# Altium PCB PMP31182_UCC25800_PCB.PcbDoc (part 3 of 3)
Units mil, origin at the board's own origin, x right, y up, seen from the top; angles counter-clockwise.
Board outline 4922 x 2266 mil, 4 copper layers (Top Layer, Signal Layer 1, Signal Layer 2, Bottom Layer), stack 77.9 mil thick; 172 components, 94 nets, 533 pads, 516 vias.
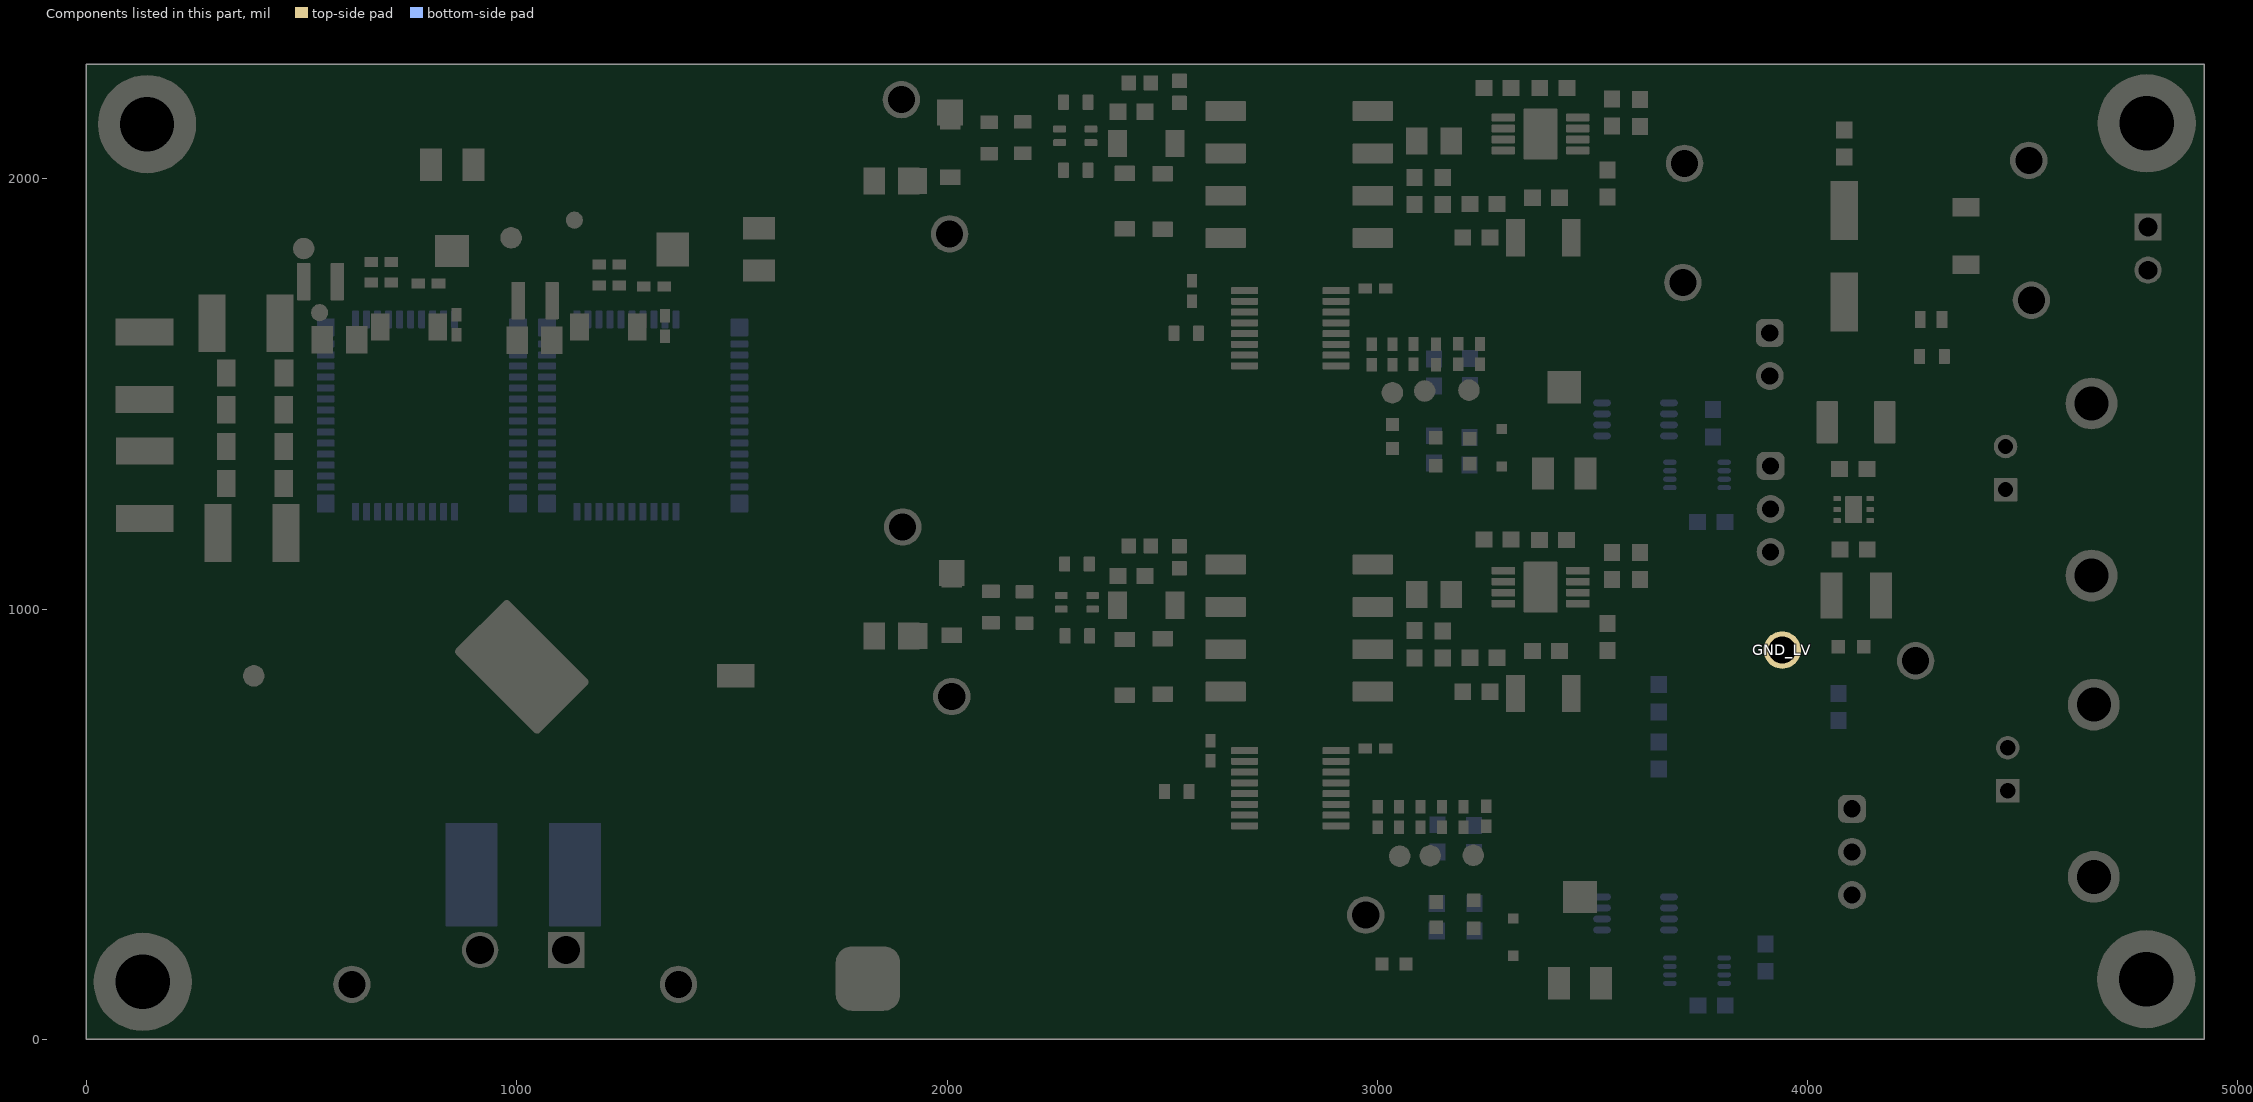
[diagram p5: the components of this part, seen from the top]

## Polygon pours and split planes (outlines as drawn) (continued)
NetT2_1 on Signal Layer 2 "NETT2_1_L03_P146" (solid, pour order 146): 3255,2078 3260,2083 3260,2107 3171.93,2195.07 3050.07,2195.07 3044,2187 3044,2138 3051,2131 3169,2131 3222,2078
HVBUS on Signal Layer 2 "HVBUS_L03_P054" (solid, remove dead copper, pour order 54): 376,22 317.88,64 317.88,192.12 79.88,430.12 79.88,1709.88 95,1725 342,1725 476,1591 476,1530 1406.59,1530 1491.2,1635.68 1531.32,1635.68 1538.88,1628.12 1538.88,1226.88 1525,1213 935,1213 758.88,1036.88 758.88,470.68 763.88,470.68 814.88,419.68 953.88,419.68 953.88,417.99 977.88,393.99 977.88,60 928,22
SW on Signal Layer 2 "SW_L03_P002" (solid, remove dead copper, pour order 2): 2691,653 2713,631 2713,484 2700,471 2475.05,471 1607,1289.18 1607,1637.45 1530.46,1714 1474,1714 1354,1594 984,1594 973,1605 973,1865 1022,1914 1530,1914 1960,1484 2586.56,857.45 2586.56,757.44
GND_LV on Signal Layer 2 "Signal Layer 1-GND_LV" (solid, pour order 158): 4759,1574 4859,1474 4859,415 4466,22 3172,22 3110,84 3110,269 3005,374 3005,441 2900,441 2898,439 2898,490 2996.53,490 3008,501.47 3008,1242 2937,1242 2936,1241 2934,1243 2934,1310 2987,1310 3008,1331 3008,1493 2977,1524 2977,1729 3078,1830 3078,2226.13 3091,2238 3583,2238 3841,2238 3864,2215 3864,1604.86 3895.74,1574
GND_HV on Signal Layer 2 "GND_HV_L03_P096" (solid, remove dead copper, pour order 96): 484,1655.47 484,2146 575,2237 2065,2237 2187,2237 2679,1745 2679,1579.01 2643.99,1544 2037,1544 1627,1954 957,1954 920,1917 920,1620 894,1594 545.48,1594
5V on Signal Layer 2 "5V_L03_P136" (solid, pour order 136): 4375.35,797.4 4114.35,797.4 4114.35,944.4 4118.35,948.4 4118.35,1110.4 4118.35,1156.4 4148.35,1186.4 4171.35,1186.4 4171.35,1223.4 4147.69,1247.06 4147.69,1251.4 4137.35,1251.4 4135.35,1253.4 4135.35,1263.4 4153.35,1263.4 4375.35,1263.4
GND_LV on Signal Layer 1 "Signal Layer 1-GND_LV" (solid, pour order 134): 4770,1575 4859,1486 4859,416 4466,23 3172,23 3110,85 3110,270 3005,375 3005,442 2900,442 2898,440 2898,491 2996.53,491 3008,502.47 3008,1243 2937,1243 2936,1242 2934,1244 2934,1311 2987,1311 3008,1332 3008,1488 2977,1519 2977,1744 3079,1846 3079,2228.04 3091,2239 3583,2239 3840,2239 3864,2215 3864,1603.86 3893.69,1575
GND_HV on Signal Layer 1 "GND_HV_L02_P008" (solid, remove dead copper, pour order 8): 1748,312 1748,313 1706,356 1706,1084 1606,1184 1450,1184 1420,1214 1420,1544 1390,1574 500,1574 481,1593 481,1763 470,1774 320,1774 310,1764 310,1674 283,1647 97,1647 70,1620 70,1064 90,1044 730,1044 888,1202 1251,1202 1300,1153 1300,561 1300.32,560.76 1300.32,560.32 1247,507 1099,507 1073,481 1073,50.87 1103.87,20 1922,20 1923,19 1955,51 1955,260 1903,312
SW on Top Layer "SW_L01_P176" (solid, pour order 176): 1608.82,1549.61 1644,1584.79 1824.3,1584.7 2286,1123 2286,1088 2271.51,1073.51 2271.51,1043.49 2280,1035 2280,1025 2083,1025 2056.91,1051.09 1889.91,1051.09 1608.82,1332.18
NetC22_1 on Top Layer "NETC22_1_L01_P177" (solid, pour order 177): 2457,1165.7 2463.3,1172 2646.33,1172 2690,1129 2694,1125 2694,1083 2691,1080 2605,1080 2600,1085 2600,1118 2589,1129 2463,1129 2457,1135
ISO_RET_H_B on Top Layer "ISO_RET_H_B_L01_P178" (solid, pour order 178): 2325.09,1024 2322.09,1027 2322.09,1044.56 2318.09,1048.56 2318.09,1160.09 2330,1172 2431,1172 2439,1164 2439,1106.91 2420.59,1088.5 2420.59,967.5 2437.09,951 2437.09,916.09 2434,913 2392,913 2389,916 2389,956.09 2375,970.09 2375,1020 2371,1024
ISO_15V_H_B on Top Layer "ISO_15V_H_B_L01_P181" (solid, pour order 181): 2355.61,908.92 2321.61,908.92 2318.61,911.92 2318.61,987.92 2323.61,992.92 2323.61,1005.92 2325.61,1007.92 2351.61,1007.92 2358.61,1000.92 2358.61,911.92
ISO_15V_H_B on Top Layer "ISO_15V_H_B_L01_P180" (solid, pour order 180): 2441,1060.67 2443.33,1058.33 2497.67,1058.33 2508,1048 2508,982 2477,951 2477,919 2480,916 2522,916 2525,919 2525,943 2552,970 2552,1073 2558.7,1079.7 2558.7,1111 2556.7,1113 2524,1113 2507,1096 2446,1096 2441,1091 2441,1063
NetD1_2 on Top Layer "NETD1_2_L01_P179" (solid, pour order 179): 2389,780 2383,786 2383,810 2391,818 2491,818 2602.5,929.5 2691,929.5 2694,926.5 2694,889.5 2689,884.5 2625.5,884.5 2521,780
ISO_15V_H on Top Layer "ISO_15V_H_L01_P175" (solid, pour order 175): 1885.5,971 1897.5,983 2066.85,983 2226.5,983 2251.5,1008 2276.5,1008 2279.5,1005 2279.5,983 2279.5,960 2286.5,953 2286.5,752 2264.5,730 1905.5,730 1885.5,750
GND_LV on Top Layer "Top Layer-GND_LV" (solid, pour order 166): 3198,1190 3207,1181 3207,1126 3260,1073 3340,1073 3340,1101 3340.01,1125.99 3326,1140 3294,1140 3291,1143 3291,1181 3294,1184 3392,1184 3397,1179 3397,1131 3419,1109 3419,984 3479.54,923.46 3576.46,923.46 3585,914.91 3585,782 3562,759 3431,759 3426,764 3426,860 3404,882 3404,929 3340,993 3340,1051 3336,1055 3231,1055 3203,1083 3133,1083 3117,1067 3117,1007 3153,971 3170,971 3173,968 3173,933 3170,930 3074,930 3067,937 3067,1065 3069,1067 3081,1067 3101.5,1087.5 3101.5,1131.5 3073,1160 3073,1181 3082,1190
15V_F on Top Layer "Top Layer-15V_F" (solid, pour order 173): 3381,704 3348.69,736.31 3348.69,845.99 3381,878.3 3381,921 3320,982 3320,1017 3317,1020 3237,1020 3211,1020 3197,1034 3197,1063 3195,1065 3149,1065 3147,1063 3147,1005 3150,1002 3171,1002 3259,914 3259,847 3242,830 3242,647 3419,470 3592.5,470 3623,470 3723,470 3790,470 3817,505.67 3817,750 3818,751 3817,751 3817,1580 3818,1580 3850,1610 3939,1610 3988,1561 4264,1561 4275.44,1572.44 4275.44,1797.56 4268,1805 3633,1805 3591,1805 3559,1773 3403,1773 3381,1795 3347,1829 3347,1900 3381,1934 3381,1972 3320,2033 3320,2071 3317,2074 3237,2074 3211,2074 3197,2088 3197,2117 3195,2119 3149,2119 3147,2117 3147,2059 3150,2056 3171,2056 3259,1968 3259,1901 3242,1884 3242,1740 3259,1723 3355,1627 3557,1627 3645,1539 3645,959 3645,773.01 3575.99,704
NetR11_1 on Top Layer "NETR11_1_L01_P171" (solid, pour order 171): 3434.46,1137 3439,1132.46 3439,1085.5 3444,1080.5 3494,1080.5 3521.5,1108 3560,1108 3564,1112 3564,1151 3561,1154 3486,1154 3458,1182 3422,1182 3420,1180 3420,1140.5 3423.5,1137
NetC34_1 on Top Layer "NETC34_1_L01_P170" (solid, pour order 170): 3623,1089 3628,1084 3628,1054 3623,1049 3518,1049 3512,1055 3440,1055 3439,1056 3439,1072 3440,1073 3512,1073 3528,1089
NetT1_1 on Top Layer "NETT1_1_L01_P168" (solid, pour order 168): 3073,1141 3079,1135 3079,1088 3072,1081 2944,1081 2942,1083 2942,1133 2950,1141 3059,1141
NetC8_2 on Top Layer "NETC8_2_L01_P167" (solid, pour order 167): 3218,791 3216,789 3130,789 3035,884 2945,884 2942,887 2942,925 2947,930 3035,930 3059,906 3228,906 3235,899 3235,869 3218,852
ISO_15V_L_B on Top Layer "ISO_15V_L_B_L01_P164" (solid, pour order 164): 2352,1993 2318,1993 2315,1996 2315,2072 2320,2077 2320,2090 2322,2092 2348,2092 2355,2085 2355,1996
ISO_RET_L_B on Top Layer "ISO_RET_L_B_L01_P165" (solid, pour order 165): 2322,2108 2319,2111 2319,2128.56 2315,2132.56 2315,2234 2327,2246 2434,2246 2439,2241 2439,2211 2439,2194 2417.5,2172.5 2417.5,2051.5 2437,2032 2437,1999 2435,1997 2391,1997 2388,2000 2388,2038 2375,2051 2375,2103 2370,2108
ISO_15V_L_B on Top Layer "ISO_15V_L_B_L01_P163" (solid, pour order 163): 2441,2172 2444,2175 2505,2175 2524,2194 2556.7,2194 2558.7,2192 2558.7,2160.7 2552,2154 2552,2051 2525,2024 2525,2000 2522,1997 2480,1997 2477,2000 2477,2032 2508,2063 2508,2129 2500,2137 2442.75,2137 2441,2139.33 2441,2144
NetC67_1 on Top Layer "NETC67_1_L01_P162" (solid, pour order 162): 3623,2142 3628,2137 3628,2105 3625,2102 3518,2102 3512,2108 3440,2108 3439,2109 3439,2125 3440,2126 3512,2126 3528,2142
GND_LV on Top Layer "Top Layer-GND_LV" (solid, pour order 114): 3079,2228.04 3088.96,2238.3 3210.7,2238.3 3220,2229 3220,2166 3260,2126 3340,2126 3340,2154 3340.01,2178.99 3327,2192 3293,2192 3291,2194 3291,2229 3293,2231 3395,2231 3397,2229 3397,2184 3419,2162 3419,2037 3479.54,1976.46 3576.46,1976.46 3645,2045 3645,2215 3669,2238 3934,2238 3934.27,2237.73 4621.71,2238.29 4638,2222 4638,2023 4637.3,2023 4674,1986.3 4827.7,1986.3 4858,1956 4858,1867 4846,1855 4489,1855 4250,2094 3965,2094 3939.55,2067.55 3939.55,1927.55 3925,1913 3637,1913 3539,1815 3431,1815 3423,1823 3423,1916 3404,1935 3404,1982 3340,2046 3340,2104 3336,2108 3249,2108 3221,2136 3133,2136 3117,2120 3117,2060 3116,2059 3151,2024 3170,2024 3173,2021 3173,1986 3170,1983 3074,1983 3067,1990 3067,2118 3069,2120 3079,2120 3096.5,2137.5 3096.5,2196 3079,2213.5
NetR29_1 on Top Layer "NETR29_1_L01_P160" (solid, pour order 160): 3431.39,2189 3438,2182.39 3438,2139 3443,2134 3493,2134 3525,2166 3559,2166 3564,2171 3564,2202 3561,2205 3484,2205 3460,2229 3424,2229 3421,2226 3421,2192 3424,2189
NetC59_2 on Top Layer "NETC59_2_L01_P161" (solid, pour order 161): 3218,1845 3216,1843 3130,1843 3035,1938 2945,1938 2942,1941 2942,1979 2947,1984 3035,1984 3059,1960 3228,1960 3235,1953 3235,1923 3218,1906
NetT2_1 on Top Layer "NETT2_1_L01_P159" (solid, pour order 159): 3074,2195 3080,2189 3080,2142 3073,2135 2945,2135 2943,2137 2943,2185 2953,2195 3060,2195
NetD4_2 on Top Layer "NETD4_2_L01_P156" (solid, pour order 156): 2372,1863 2363,1872 2363,1896 2373,1906 2515,1906 2592,1983 2691,1983 2694,1980 2694,1943 2689,1938 2600,1938 2525,1863
ISO_15V_L on Top Layer "ISO_15V_L_L01_P154" (solid, pour order 154): 2247,2092 2230,2075 2079,2075 2030,2026 1885,2026 1885,1845 1911,1819 2273,1819 2283,1829 2283,2030.5 2275.5,2038 2275.5,2079.5 2275.5,2089.5 2273,2092
NetC60_1 on Top Layer "NETC60_1_L01_P153" (solid, pour order 153): 2460,2206 2457,2209 2457,2243 2459,2245 2628.05,2245 2690,2184 2694,2180 2694,2138 2691,2135 2605,2135 2600,2140 2600,2197 2591,2206
SW on Top Layer "Top Layer-No Net" (solid, pour order 151): 1301,1685 1299,1687 1292.24,1687 1259,1687 cw(c1258.98,1695.8) 1250.18,1695.82 1250.18,1731.5 1257,1738 1308.8,1738 1311,1741 1311,1761.81 1306,1766 1226.81,1766 1223,1762.18 1223,1740 1233.18,1729.82 1233.17,1693.57 1233.17,1682.07 1223,1671.9 1185,1671.9 1177.05,1663.95 1176.73,1618.6 1172,1615.42 1110.58,1615.42 1106.12,1619.88 1106.11,1656.49 1098.12,1669.79 1098.12,1759.88 1096.19,1761.81 1068.81,1761.81 1067,1760 1067,1670.21 1056.12,1656.65 1056.12,1595.32 1069.33,1588.58 1351.95,1588.58 ccw(c1351.95,1596.8) 1360.18,1596.8 1360.18,1646.58 1355.14,1651 1312.11,1651 1301,1661
GND_HV on Top Layer "Top Layer-GND_HV" (solid, pour order 150): 924.5,2070 921.5,2073 877.5,2073 874.5,2070 874.5,1991 cw(c865.51,1990.99) 865.5,1982 763.37,1982 749.5,1968.13 749.5,1778.65 741.56,1770.72 701.5,1770.72 697.22,1770.72 693.5,1767 693.5,1740 704.5,1729 719.5,1714 719.5,1698 712.5,1691 712.5,1618 656.5,1618 653.5,1621 653.5,1655 651.5,1657 607.5,1657 603.5,1653 603.5,1599 608.5,1594 894.5,1594 900.5,1600 900.5,1644 890.5,1654 845.5,1654 838.35,1661.16 838.35,1686 749.5,1686 737.5,1698 737.5,1715.41 787.5,1745.19 787.5,1948 911.5,1948 ccw(c911.51,1960.99) 924.5,1961
GND_LV on Top Layer "GND_LV_L01_P149" (solid, pour order 149): 3900,1495 3900,745 3994,651 4518,651 4534,702 4534,745 4534,1454 4489,1499 3903,1499
NetC11_2 on Top Layer "NETC11_2_L01_P148" (solid, pour order 148): 647,1845 660,1859 660,2076 701,2117 1538,2117 1692,1963 1855,1963 1855,2026 1757,2026 1577,2206 627,2206 585,2164 585,1857 597,1845
GND_LV on Top Layer "GND_LV_L01_P139" (solid, pour order 139): 3117.25,639.25 3126,648 3126,695 3117.75,703.25 3019,703.25 3004,688.25 3004,662.22 2996.03,654.25 2925,654.25 2925,639.25
GND_LV on Top Layer "GND_LV_L01_P138" (solid, pour order 138): 3104,1708 3114,1718 3114,1759 3101,1772 3019,1772 3004,1757 3004,1730.97 2996.03,1723 2925,1723 2925,1708
15V on Top Layer "15V_L01_P104" (solid, pour order 104): 4846,1821 4859,1807 4859,1576 4846,1563 4312,1563 4300,1575 4300,1812 4309,1821
5V on Top Layer "5V_L01_P118" (solid, pour order 118): 4345,1263 4375,1233 4376,1231 4376,822 4351,797 4136,797 4115,818 4115,944 4144,973 4144,1085 4119,1110 4119,1156 4149,1186 4172,1186 4172,1227.34 4148.34,1251 4138,1251 4136,1253 4136,1263
GND_HV on Top Layer "GND_HV_L01_P112" (solid, pour order 112): 1734,2233 1748,2247 1758,2247 2267,2247 2283,2231 2283,2162 2276,2155 2276,2113 2271,2108 2248,2108 2241,2115 1803,2115 1734,2184
VNEG_L on Top Layer "VNEG_L_L01_P097" (solid, remove dead copper, pour order 97): 579,1594 586,1601 586,1615 575,1626 575,1674 567,1682 567,1698 554,1711 536,1711 500,1675 500,1600 506,1594
SW on Top Layer "SW_L01_P088" (solid, remove dead copper, pour order 88): 975,1170 810,1005 810,644 830,624 1210,624 1238.29,652.29 1238.29,1159.71 1228,1170
GND_HV on Top Layer "GND_HV_L01_P082" (solid, remove dead copper, pour order 82): 418,1784 428,1794 471,1794 481,1784 481,1667 481,1593 550,1524 1309,1524 1391,1442 1391,1216 1446,1161 1629,1161 1705,1085 1705,356 1748,312 1903,312 1955,260 1955,51 1923,19 1922,20 1705,20 1104.63,20 1074,56.55 1074,482 1099,507 1247,507 1299,559 1300,561 1300,1184.41 1254.37,1230.04 916.04,1230.04 790,1104 433,1104 418,1117.75
HVBUS on Top Layer "HVBUS_L01_P032" (solid, remove dead copper, pour order 32): 60,457 60,1234 70,1244 250,1244 270,1264 270,1584 250,1604 70,1604 60,1614 60,1720 74,1734 340,1734 350,1724 350,1068 374,1044 700,1044 740.14,1003.86 740.14,559 793,508 935,508 959,484 959,59 921,21 343.14,21 310,64.02 310,207
GND_HV on Top Layer "GND_HV_L01_P030" (solid, remove dead copper, pour order 30): 70,1524 60,1514 60,1344 70,1334 201,1334 208,1341 208,1514 198,1524

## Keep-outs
Keep-Out Layer:
  lines w10: 2136.71,2261 2141.71,2266 4922,2266 4922,0 3006,0
  text ".Layer_Name" at 502,-792.77 h30

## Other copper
Signal Layer 1:
  pour cut-out: 267,1132.33 267,1164.5 244.91,1178 130.3,1178 111.84,1162.73 111.84,1135 133.17,1119 162.28,1119 247,1119
  pour cut-out: 266,1227.07 306,1227.07 316,1241 316,1578.62 302.49,1595.51 269.25,1595.51 257,1579.17 257,1526.56 257,1241.86
Signal Layer 2:
  pour cut-out: 536,1336 546,1346 546,1411.23 538.99,1420 481.25,1420 473,1409 473,1348.18 480.88,1336
  pour cut-out: 534,1125 546,1137 546,1202.23 537.39,1213 482.75,1213 472,1198.67 472,1140.73 482.18,1125
  pour cut-out: 534,1227 547,1240 547,1302.98 537.39,1315 482.75,1315 473,1302 473,1241.18 482.18,1227
  pour cut-out: 536,1443 547,1454 547,1516.98 538.99,1527 481.25,1527 472,1514.67 472,1456.73 480.88,1443
  pour cut-out: 108,1399 119,1388 200.75,1388 212,1397 212,1454.75 197,1466 124.73,1466 108,1455.18

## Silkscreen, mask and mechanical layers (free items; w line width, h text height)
Top Overlay:
  lines w10: 556,1866 556,1884 557,1885 ; 577,1885 557,1885 ; 623,1819 557,1885 ; 2339,1880 2355,1896 2355,2020 2375,2040 ; 2339,1883 2339,1897 ; 2340,1880 2358,1880 ; 2358,1210 2368,1220 2371,1220 ; 2371,1124 2371,1161 ; 2371,1142.5 2371,1219 2372,1220 ; 2372,1217 2372,1220 2382,1210 ; 3085,1652 3085,1689 3159,1763 ; 3140,1763 3158,1763 ; 3159,1746 3159,1760
  text "-" at 4727.87,1978 h150 r90
  text "+" at 4658,1621.45 h150
  text "PWM BOT" at 4349.33,1231 h60 r90
  text "PWM TOP" at 4352,477 h60 r90
  text "Load_GND" at 1694,242 h60
  text "Max DC Input:  / 520 V/25 A" at 804,44 h60
  text "PMP31182_UCC25800Q1" at 3566,37 h60
Bottom Overlay:
  text "Max DC Input:  / 520 V/25 A" at 1371,45 h30
Top Paste:
  text ".Layer_Name" at 5093,3542.51 h30
Bottom Paste:
  text ".Layer_Name" at 5093,3542.51 h30
Top Solder:
  text ".Layer_Name" at 5093,3542.51 h30
Bottom Solder:
  text ".Layer_Name" at 5093,3542.51 h30
M1 Board Outline:
  the board outline again, w15
  text ".Layer_Name" at 502,-792.77 h30
M2 Board Dimensions:
  rectangle: -70,-219.27 55,-94.27
  rectangle: 50,-344.77 425,-219.77
  lines w7: -75,-94.77 -75,-344.77 925,-344.77 925,-94.77 ; -70,-219.27 930,-219.27 ; -70,-94.27 930,-94.27 ; 50,-344.77 50,-94.77 ; 175,-344.77 175,-94.77 ; 425,-344.77 425,-94.77 ; 675,-344.77 675,-94.77
  lines w10: -14.57,3 2986.43,3 ; 0,604 0,2266 4922,2266 4922,0 3624,0 3619,5
  text ".Layer_Name" at 502,-792.77 h30
M3 3D STEP Top:
  lines w10: 0,9 0,2266 4922,2266 4922,9 0,9
  text ".Layer_Name" at 502,-792.77 h30
M4 3D STEP Bottom:
  lines w10: 588.72,2260 583.69,2256.46 208.56,2256.46 0,2139.46 0,0 4922,0 4922,2266 2136.21,2266 2130.21,2260 ; 524,1188 1550,1188 1550,1730 524,1730 524,1188
M5 Assembly Top:
  lines w10: -367,-864.44 6233,-864.44 ; -367,-661.11 6235,-661.11 ; -367,-457.77 -367,-1067.77 3638,-1067.77 6235,-1067.77 6235,-457.77 -366.5,-457.77 -366.5,-1067.77 ; 2098,-1067.77 2098,-457.77 ; 3365,-661.11 3365,-457.77 ; 4205,-661.11 4205,-457.77 ; 4224.5,3267.5 5800,3267.5 ; 4827,-1074.27 4827,-871.44
  text "PCB VIEWED FROM TOP SIDE" at 4287.5,3745.33 h30
  text "IGNORE ->" at 4287.5,3542.51 h30
  text "PLOT NAME =" at 4287.5,3336.67 h30
  text "COMPONENTS MARKED 'DNP' SHOULD NOT BE POPULATED." at 1078.5,-252.77 h30
  text "ASSEMBLY VARIANT:" at 1078,-368.27 h30
  text ".VariantName" at 2114,-368.27 h30
  text "BOARD #:" at 2173,-589.94 h30
  text ".PRJ_Number" at 2718.5,-589.94 h30
  text "REV:" at 3563,-589.94 h30
  text ".PCB_Rev" at 3854.5,-589.94 h30
  text "SVN REV:" at 4401,-589.94 h30
  text ".VersionControl_RevNumber" at 4907,-589.94 h30
  text ".plot_File_Name" at 502,-998.61 h30
  text "GENERATED    :" at 2175,-998.61 h30
  text ".Print_Date" at 3044.5,-998.61 h30
  text ".Print_Time" at 3773.5,-998.61 h30
  text "TEXAS INSTRUMENTS" at 5038,-998.61 h30
M6 Assembly Bottom:
  lines w10: -367.5,-661.61 6234.5,-661.61 ; -365.5,-864.94 6234.5,-864.94 ; 1662.5,-661.61 1662.5,-458.27 ; 2502.5,-661.61 2502.5,-458.27 ; 3769.5,-1068.27 3769.5,-458.27 ; 4658.5,-1068.27 6234,-1068.27 6234,-458.27 -367.5,-458.27 -367.5,-1068.27 2229.5,-1068.27 6234.5,-1068.27 6234.5,-458.27 ; 5631.5,3260.5 5631.5,3463.33
  text ".VersionControl_RevNumber" at 5551.5,3744.83 h30
  text "TEXAS INSTRUMENTS" at 5420.5,3336.17 h30
  text "COMPONENTS MARKED 'DNP' SHOULD NOT BE POPULATED." at 6724,-256.27 h30
  text ".VariantName" at 5680,-372.27 h30
  text "ASSEMBLY VARIANT:" at 6719,-372.27 h30
  text "SVN REV:" at 1466.5,-590.44 h30
  text ".PCB_Rev" at 2013,-590.44 h30
  text "REV:" at 2304.5,-590.44 h30
  text ".PRJ_Number" at 3149,-590.44 h30
  text "BOARD #:" at 3694.5,-590.44 h30
  text "PCB VIEWED FROM BOTTOM SIDE" at 6171,-590.44 h30
  text "IGNORE ->" at 2472.85,-792.77 h30
  text ".Print_Time" at 2094,-999.11 h30
  text ".Print_Date" at 2823,-999.11 h30
  text "GENERATED    :" at 3692.5,-999.11 h30
  text ".plot_File_Name" at 5365.5,-999.11 h30
  text "PLOT NAME =" at 6171,-999.11 h30
M9 Title Sheet:
  drawing of 57 lines, arcs and shapes, not listed
  text "1" at 664.84,8102.23 h30
  text "2" at 3160.5,8102.23 h30
  text "3" at 5649.84,8102.23 h30
  text "4" at 8156.51,8102.23 h30
  text "5" at 10655.5,8102.23 h30
  text "6" at 13160.5,8102.23 h30
  text "A" at -491.5,6959.23 h30
  text "A" at 14308.5,6959.23 h30
  text "B" at -491.5,4579.23 h30
  text "B" at 14308.5,4579.23 h30
  text "1" at 5255.84,3137.5 h30
  text "C" at 14308.5,2204.23 h30
  text "PROJECT TITLE:" at 11268.5,343.23 h30
  text "LMG342xRx0" at 11318.5,209.9 h30
  text "DESIGNED FOR:" at 11268.5,42.23 h30
  text ".PRJ_Customer" at 11318.5,-97.77 h30
  text "D" at -491.5,-165.77 h30
  text "D" at 14308.5,-165.77 h30
  text "FILE NAME:" at 11268.5,-257.77 h30
  text ".PCB_File_Name_No_Path" at 11318.5,-377.77 h30
  text "Texas Instruments (TI) and/or its licensors do not warrant the accuracy or completeness of this specification" at 6299,-539.61 h30
  text "ENGINEER:" at 11268.5,-547.77 h30
  text "LAYOUT BY:" at 12773.5,-547.77 h30
  text "or any information contained therein. TI and/or its licensors do not warrant that this design will meet" at 6254.02,-652.28 h30
  text "Rui Gao" at 11318.5,-702.77 h30
  text "Rui Gao" at 12824,-702.77 h30
  text "the specifications, will be suitable for your application or fit for any particular purpose, or will operate in" at 6254.02,-764.94 h30
  text ".Layer_Name" at 502,-792.77 h30
  text "ALTIUM DESIGNER VERSION:" at 12773.5,-857.77 h30
  text "an implementation. TI and/or its licensors do not warrant that the design is production worthy. You should" at 6254.02,-877.61 h30
  text "completely validate and test your design implementation to confirm the system functionality for your application." at 6299,-990.27 h30
  text ".print_Scale" at 11318.5,-991.1 h30
  text ".Application_BuildNumber" at 12824,-991.1 h30
  text "2" at 3160.5,-1197.77 h30
  text "3" at 5649.84,-1197.77 h30
  text "4" at 8156.51,-1197.77 h30
  text "5" at 10655.5,-1197.77 h30
  text "6" at 13160.5,-1197.77 h30
M10 Fab Notes:
  drawing of 185 lines, arcs and shapes, not listed
  text "DESIGN INFORMATION" at 12306.02,5975.73 h30
  text "MIN. TRACK WIDTH:" at 11661.46,5795.73 h30
  text "6" at 12757.7,5795.73 h30
  text "MIL" at 12912.46,5795.73 h30
  text "MIN. CLEARANCE:" at 11661.46,5663.73 h30
  text "5.5" at 12697.7,5663.73 h30
  text "MIL" at 12912.46,5663.73 h30
  text "MIN. VIA PAD SIZE:" at 11661.46,5531.73 h30
  text "16" at 12727.71,5531.73 h30
  text "MIL" at 12912.46,5531.73 h30
  text "4 MIL" at 12356.46,5390.01 h30
  text "MINIMUM ANNULAR RING" at 11332.23,5385.73 h30
  text "PER" at 11532.23,5267.73 h30
  text "IPC-D-275 CLASS 2 LEVEL C" at 11752.23,5267.73 h30
  text "MIL, HOLES" at 13240.46,5155.44 h30
  text "+/-" at 12848,5154.73 h30
  text "+/-" at 13702,5154.73 h30
  text "REGISTRATION TOLERANCES:" at 11332.23,5149.73 h30
  text "METAL" at 12532,5149.73 h30
  text "MIL" at 14057.46,5149.73 h30
  text "MATERIAL:" at 11257.46,4940.27 h30
  text "FR-4 High Tg" at 12243.9,4799.93 h30
  text "FR-408" at 11678.46,4791.36 h30
  text "X" at 12090.46,4791.36 h30
  text "OTHER" at 13166.46,4791.36 h30
  text "X" at 11877.46,4636.36 h30
  text "78.7 MIL (2.0 mm) +/-10%" at 11998.56,4628.65 h30
  text "THICKNESS:" at 11332.23,4624.36 h30
  text "OTHER" at 13283.46,4624.36 h30
  text "TOLERANCE:" at 11332.23,4466.36 h30
  text "X" at 12171.54,4466.36 h30
  text "ANSI IPC-6012 TYPE 3 CLASS 2" at 12358.48,4466.36 h30
  text "OTHER +/-" at 12358.46,4310.36 h30
  text "BOW & TWIST:" at 11332.23,4153.36 h30
  text "X" at 12171.54,4153.36 h30
  text "ANSI IPC-6012 TYPE 3 CLASS 2" at 12358.48,4153.36 h30
  text "OTHER +/-" at 12358.46,3994.86 h30
  text "DRILLING:" at 11257.46,3856.36 h30
  text "REFERENCE:" at 11332.23,3739.36 h30
  text "X" at 11980.46,3739.36 h30
  text "AS SHOWN" at 12167.46,3739.36 h30
  text "X" at 12881.46,3739.36 h30
  text "NC_DRILL FILES" at 13018.46,3739.36 h30
  text "PTH MIN COPPER THICKNESS:" at 11332.23,3581.36 h30
  text "X" at 12674.46,3581.36 h30
  text "1MIL" at 12819.46,3581.36 h30
  text "OTHER" at 13316.46,3581.36 h30
  text "BOARD FINISH:" at 11257.46,3422.36 h30
  text "SILKSCREEN:" at 11412.68,3304.36 h30
  text "X" at 12361.46,3304.36 h30
  text "TOP" at 12487.46,3304.36 h30
  text "X" at 12871.46,3304.36 h30
  text "BOTTOM" at 12998.46,3304.36 h30
  text "SILKSCREEN COLOR:" at 11412.68,3137.36 h30
  text "X" at 12360.42,3137.36 h30
  text "WHITE" at 12487.46,3137.36 h30
  text "OTHER" at 12998.46,3137.36 h30
  text "SOLDER RESIST COLOR:" at 11412.68,2967.36 h30
  text "X" at 11980.42,2808.17 h30
  text "GREEN" at 12107.46,2808.17 h30
  text "BLUE" at 12698.46,2808.17 h30
  text "OTHER" at 13236.46,2808.17 h30
  text "IMMERSION GOLD (ENIG)" at 12318.46,2619.65 h30
  text "ENEPIG" at 13656,2616.36 h30
  text "SURFACE FINISH:" at 11257.46,2615.36 h30
  text "X" at 12131.51,2615.36 h30
  text "IMM. TIN/SILVER OR EQUIV" at 11587,2458.36 h30
  text "OTHER" at 13018.46,2458.36 h30
  text "X" at 12134,2287 h30
  text "ARRAY/PANEL:" at 11257.46,2279.36 h30
  text "CUT AND TRIM PER MECH LAYER 1" at 12318.46,2275.08 h30
  text "N.C. ROUTE" at 12318.46,2123.36 h30
  text "V. SCORE" at 13184.46,2123.36 h30
  text "CERTIFICATION:" at 11257.46,1986.36 h30
  text "MATERIALS AND WORKMANSHIP FOR ALL PCBS" at 11982.46,1986.36 h30
  text "TO MEET OR EXCEED THE REQUIREMENTS OF:" at 11982.46,1888.36 h30
  text "X" at 11608.96,1751.86 h30
  text "ANSI IPC-A-600F CLASS ->" at 11747.96,1751.86 h30
  text "X" at 13387.02,1751.86 h30
  text "2" at 13505.96,1751.86 h30
  text "1" at 13190.96,1750.36 h30
  text "3" at 13859.96,1750.36 h30
  text "X" at 11611.02,1592.36 h30
  text "UL 94V-0" at 11747.96,1592.36 h30
  text "X" at 12423.02,1592.36 h30
  text "RoHS" at 12559.96,1592.36 h30
  text "OTHER" at 13204.37,1592.36 h30
  text "PER ORDER" at 13601.42,1592.36 h30
  text "ADDITIONAL REQUIREMENTS:" at 11257.46,1451.36 h30
  text "MICROSECTION:" at 11332.23,1336.36 h30
  text "YES" at 12237.96,1336.36 h30
  text "REQUIRED" at 13099.46,1180.22 h30
  text "BARE BOARD ELEC. TEST:" at 11332.23,1177.36 h30
  text "NONE" at 12637.96,1177.36 h30
  text "X" at 12972.46,1177.36 h30
  text "PER ORDER" at 13691.46,1177.36 h30
  text "MANUFACTURER'S UL:" at 11332.23,1020.36 h30
  text "RAIL" at 12497.96,1016.08 h30
  text "METAL" at 12989.78,1016.08 h30
  text "X" at 13365,1015.73 h30
  text "SILK" at 13501.46,1016.08 h30
  text ".Layer_Name" at 502,-792.77 h30
M11 Gerber Information:
  lines w10: -367,-864.44 6233,-864.44 ; -367,-661.11 6235,-661.11 ; -367,-457.77 -367,-1067.77 3638,-1067.77 6235,-1067.77 6235,-457.77 -366.5,-457.77 -366.5,-1067.77 ; 2098,-1067.77 2098,-457.77 ; 3365,-661.11 3365,-457.77 ; 4205,-661.11 4205,-457.77 ; 4224.5,3267.5 5800,3267.5 ; 4827,-1074.27 4827,-871.44
  text "PLOT NAME =" at 4287.5,3336.67 h30
  text "BOARD #:" at 2173,-589.94 h30
  text ".PRJ_Number" at 2718.5,-589.94 h30
  text "REV:" at 3563,-589.94 h30
  text ".PCB_Rev" at 3854.5,-589.94 h30
  text "SVN REV:" at 4401,-589.94 h30
  text ".VersionControl_RevNumber" at 4907,-589.94 h30
  text ".plot_File_Name" at 502,-998.61 h30
  text "GENERATED    :" at 2175,-998.61 h30
  text ".Print_Date" at 3044.5,-998.61 h30
  text ".Print_Time" at 3773.5,-998.61 h30
  text "TEXAS INSTRUMENTS" at 5038,-998.61 h30
M12 Stackup:
  drawing of 295 lines, arcs and shapes, not listed
  text "Layer" at 9552.84,7738.23 h60
  text "Name" at 9962.76,7738.23 h60
  text "Material" at 10902.5,7738.23 h60
  text "Thickness" at 11762.26,7738.23 h60
  text "Constant" at 12412.1,7738.23 h60
  text "Board Layer Stack" at 12981.96,7738.23 h60
  text "Top Overlay" at 9962.76,7618.23 h60
  text "Top Solder" at 9962.76,7498.23 h60
  text "Solder Resist" at 10902.5,7498.23 h60
  text "0.40mil" at 11762.26,7498.23 h60
  text "3.5" at 12412.1,7498.23 h60
  text "1" at 9552.84,7378.23 h60
  text "Top Layer" at 9962.76,7378.23 h60
  text "2.80mil" at 11762.26,7378.23 h60
  text "Dielectric 1" at 9962.76,7258.23 h60
  text "FR-4" at 10902.5,7258.23 h60
  text "4.60mil" at 11762.26,7258.23 h60
  text "4.2" at 12412.1,7258.23 h60
  text "2" at 9552.84,7138.23 h60
  text "Signal Layer 1" at 9962.76,7138.23 h60
  text "2.80mil" at 11762.26,7138.23 h60
  text "Dielectric 2" at 9962.76,7018.23 h60
  text "FR-4" at 10902.5,7018.23 h60
  text "57.50mil" at 11762.26,7018.23 h60
  text "4.2" at 12412.1,7018.23 h60
  text "3" at 9552.84,6898.23 h60
  text "Signal Layer 2" at 9962.76,6898.23 h60
  text "2.80mil" at 11762.26,6898.23 h60
  text "Dielectric 3" at 9962.76,6778.23 h60
  text "FR-4" at 10902.5,6778.23 h60
  text "4.60mil" at 11762.26,6778.23 h60
  text "4.2" at 12412.1,6778.23 h60
  text "4" at 9552.84,6658.23 h60
  text "Bottom Layer" at 9962.76,6658.23 h60
  text "2.80mil" at 11762.26,6658.23 h60
  text "Bottom Solder" at 9962.76,6538.23 h60
  text "Solder Resist" at 10902.5,6538.23 h60
  text "0.40mil" at 11762.26,6538.23 h60
  text "3.5" at 12412.1,6538.23 h60
  text "Bottom Overlay" at 9962.76,6418.23 h60
  text ".Layer_Name" at 5093,3542.51 h30
M13 Component Bodies Top:
  text ".Layer_Name" at 502,-792.77 h30
M14 Component Bodies Bottom:
  text ".Layer_Name" at 502,-792.77 h30
M15 Courtyards Top:
  text ".Layer_Name" at 502,-792.77 h30
M16 Courtyards Bottom:
  text ".Layer_Name" at 502,-792.77 h30
Drill Drawing:
  circle w10: c6502.89,409.18 r23.04
  lines w10: 6479.85,86.62 6491.37,86.62 6502.89,75.1 6514.41,86.62 6525.93,86.62 6514.41,98.14 6525.93,109.66 6514.41,109.66 6502.89,121.18 6491.37,109.66 6479.85,109.66 6491.37,98.14 6479.85,86.62 ; 6479.85,178.78 6479.85,190.3 6491.37,201.82 6479.85,213.34 6479.85,224.86 6491.37,224.86 6502.89,213.34 6514.41,224.86 6525.93,224.86 6525.93,213.34 6514.41,201.82 6525.93,190.3 6525.93,178.78 6514.41,178.78 6502.89,190.3 6491.37,178.78 6479.85,178.78 ; 6479.85,282.46 6525.93,282.46 6525.93,328.54 6479.85,328.54 6479.85,282.46 ; 6479.85,639.59 6525.93,639.59 6502.89,593.51 6479.85,639.59 ; 6479.85,708.71 6491.37,708.71 6491.37,697.19 6514.41,697.19 6514.41,708.71 6525.93,708.71 6525.93,731.75 6514.41,731.75 6514.41,743.27 6491.37,743.27 6491.37,731.75 6479.85,731.75 6479.85,708.71 ; 6479.85,812.39 6491.37,812.39 6491.37,800.87 6514.41,800.87 6514.41,812.39 6525.93,812.39 6525.93,835.43 6514.41,835.43 6514.41,846.95 6491.37,846.95 6491.37,835.43 6479.85,835.43 6479.85,812.39 ; 6479.85,904.55 6479.85,916.07 6491.37,927.59 6479.85,939.11 6479.85,950.63 6491.37,950.63 6502.89,939.11 6514.41,950.63 6525.93,950.63 6525.93,939.11 6514.41,927.59 6525.93,916.07 6525.93,904.55 6514.41,904.55 6502.89,916.07 6491.37,904.55 6479.85,904.55 ; 6479.85,1019.75 6491.37,1019.75 6502.89,1008.23 6514.41,1019.75 6525.93,1019.75 6514.41,1031.27 6525.93,1042.79 6514.41,1042.79 6502.89,1054.31 6491.37,1042.79 6479.85,1042.79 6491.37,1031.27 6479.85,1019.75 ; 6489.06,188 6489.06,194.91 6495.98,201.82 6489.06,208.73 6489.06,215.65 6495.98,215.65 6502.89,208.73 6509.8,215.65 6516.71,215.65 6516.71,208.73 6509.8,201.82 6516.71,194.91 6516.71,188 6509.8,188 6502.89,194.91 6495.98,188 6489.06,188 ; 6489.06,291.68 6516.71,291.68 6516.71,319.33 6489.06,319.33 6489.06,291.68 ; 6489.06,713.32 6495.98,713.32 6495.98,706.4 6509.8,706.4 6509.8,713.32 6516.71,713.32 6516.71,727.14 6509.8,727.14 6509.8,734.05 6495.98,734.05 6495.98,727.14 6489.06,727.14 6489.06,713.32 ; 6489.06,1024.36 6495.98,1024.36 6502.89,1017.45 6509.8,1024.36 6516.71,1024.36 6509.8,1031.27 6516.71,1038.18 6509.8,1038.18 6502.89,1045.1 6495.98,1038.18 6489.06,1038.18 6495.98,1031.27 6489.06,1024.36
  lines w12: 6437.55,44 10686.45,44 ; 6437.55,1080.81 10686.45,1080.81 ; 6828.21,-59.68 6828.21,1184.49 ; 7278.96,-59.68 7278.96,1184.49 ; 8218.94,-59.68 8218.94,1184.49 ; 8578.48,-59.68 8578.48,1184.49 ; 9095.57,-59.68 9095.57,1184.49 ; 10138.25,-59.68 10138.25,1184.49 ; 6437.55,-59.68 10686.45,-59.68 10686.45,1184.49 6437.55,1184.49 6437.55,-59.68
  text ".Layer_Name" at 5093,3542.51 h30
  text "Symbol" at 6499.76,1111.91 h49.77
  text "Quantity" at 6859.31,1111.91 h49.77
  text "Finished Hole Size" at 7310.07,1111.91 h49.77
  text "Plated" at 8250.04,1111.91 h49.77
  text "Hole Type" at 8609.59,1111.91 h49.77
  text "Drill Layer Pair" at 9126.68,1111.91 h49.77
  text "Tolerance" at 10169.36,1111.91 h49.77
  text "14" at 6859.31,1008.23 h41.47
  text "7.87mil (0.200mm)" at 7310.07,1008.23 h41.47
  text "PTH" at 8250.04,1008.23 h41.47
  text "Round" at 8609.59,1008.23 h41.47
  text "Top Layer - Bottom Layer" at 9126.68,1008.23 h41.47
  text "498" at 6859.31,904.55 h41.47
  text "10.00mil (0.254mm)" at 7310.07,904.55 h41.47
  text "PTH" at 8250.04,904.55 h41.47
  text "Round" at 8609.59,904.55 h41.47
  text "Top Layer - Bottom Layer" at 9126.68,904.55 h41.47
  text "4" at 6859.31,800.87 h41.47
  text "31.50mil (0.800mm)" at 7310.07,800.87 h41.47
  text "PTH" at 8250.04,800.87 h41.47
  text "Round" at 8609.59,800.87 h41.47
  text "Top Layer - Bottom Layer" at 9126.68,800.87 h41.47
  text "4" at 6859.31,697.19 h41.47
  text "35.04mil (0.890mm)" at 7310.07,697.19 h41.47
  text "PTH" at 8250.04,697.19 h41.47
  text "Round" at 8609.59,697.19 h41.47
  text "Top Layer - Bottom Layer" at 9126.68,697.19 h41.47
  text "8" at 6859.31,593.51 h41.47
  text "40.00mil (1.016mm)" at 7310.07,593.51 h41.47
  text "PTH" at 8250.04,593.51 h41.47
  text "Round" at 8609.59,593.51 h41.47
  text "Top Layer - Bottom Layer" at 9126.68,593.51 h41.47
  text "2" at 6859.31,489.83 h41.47
  text "43.31mil (1.100mm)" at 7310.07,489.83 h41.47
  text "PTH" at 8250.04,489.83 h41.47
  text "Round" at 8609.59,489.83 h41.47
  text "Top Layer - Bottom Layer" at 9126.68,489.83 h41.47
  text "A" at 6477.53,479.83 h46.08
  text "13" at 6859.31,386.14 h41.47
  text "63.00mil (1.600mm)" at 7310.07,386.14 h41.47
  text "PTH" at 8250.04,386.14 h41.47
  text "Round" at 8609.59,386.14 h41.47
  text "Top Layer - Bottom Layer" at 9126.68,386.14 h41.47
  text "2" at 6859.31,282.46 h41.47
  text "64.96mil (1.650mm)" at 7310.07,282.46 h41.47
  text "PTH" at 8250.04,282.46 h41.47
  text "Round" at 8609.59,282.46 h41.47
  text "Top Layer - Bottom Layer" at 9126.68,282.46 h41.47
  text "4" at 6859.31,178.78 h41.47
  text "79.13mil (2.010mm)" at 7310.07,178.78 h41.47
  text "PTH" at 8250.04,178.78 h41.47
  text "Round" at 8609.59,178.78 h41.47
  text "Top Layer - Bottom Layer" at 9126.68,178.78 h41.47
  text "4" at 6859.31,75.1 h41.47
  text "125.98mil (3.200mm)" at 7310.07,75.1 h41.47
  text "PTH" at 8250.04,75.1 h41.47
  text "Round" at 8609.59,75.1 h41.47
  text "Top Layer - Bottom Layer" at 9126.68,75.1 h41.47
  text "553 Total" at 6859.31,-28.58 h41.47
Bottom Courtyard:
  pour cut-out: 536,1443 544,1451 544,1520.73 538.99,1527 481.25,1527 475,1518.67 475,1452.09 480.88,1443

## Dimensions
0,2266 to 0,0 on M2 Board Dimensions
-75,-344.77 to 925,-344.77 on M2 Board Dimensions
0,0 to 4922,0 on M2 Board Dimensions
